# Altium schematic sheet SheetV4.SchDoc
size A1
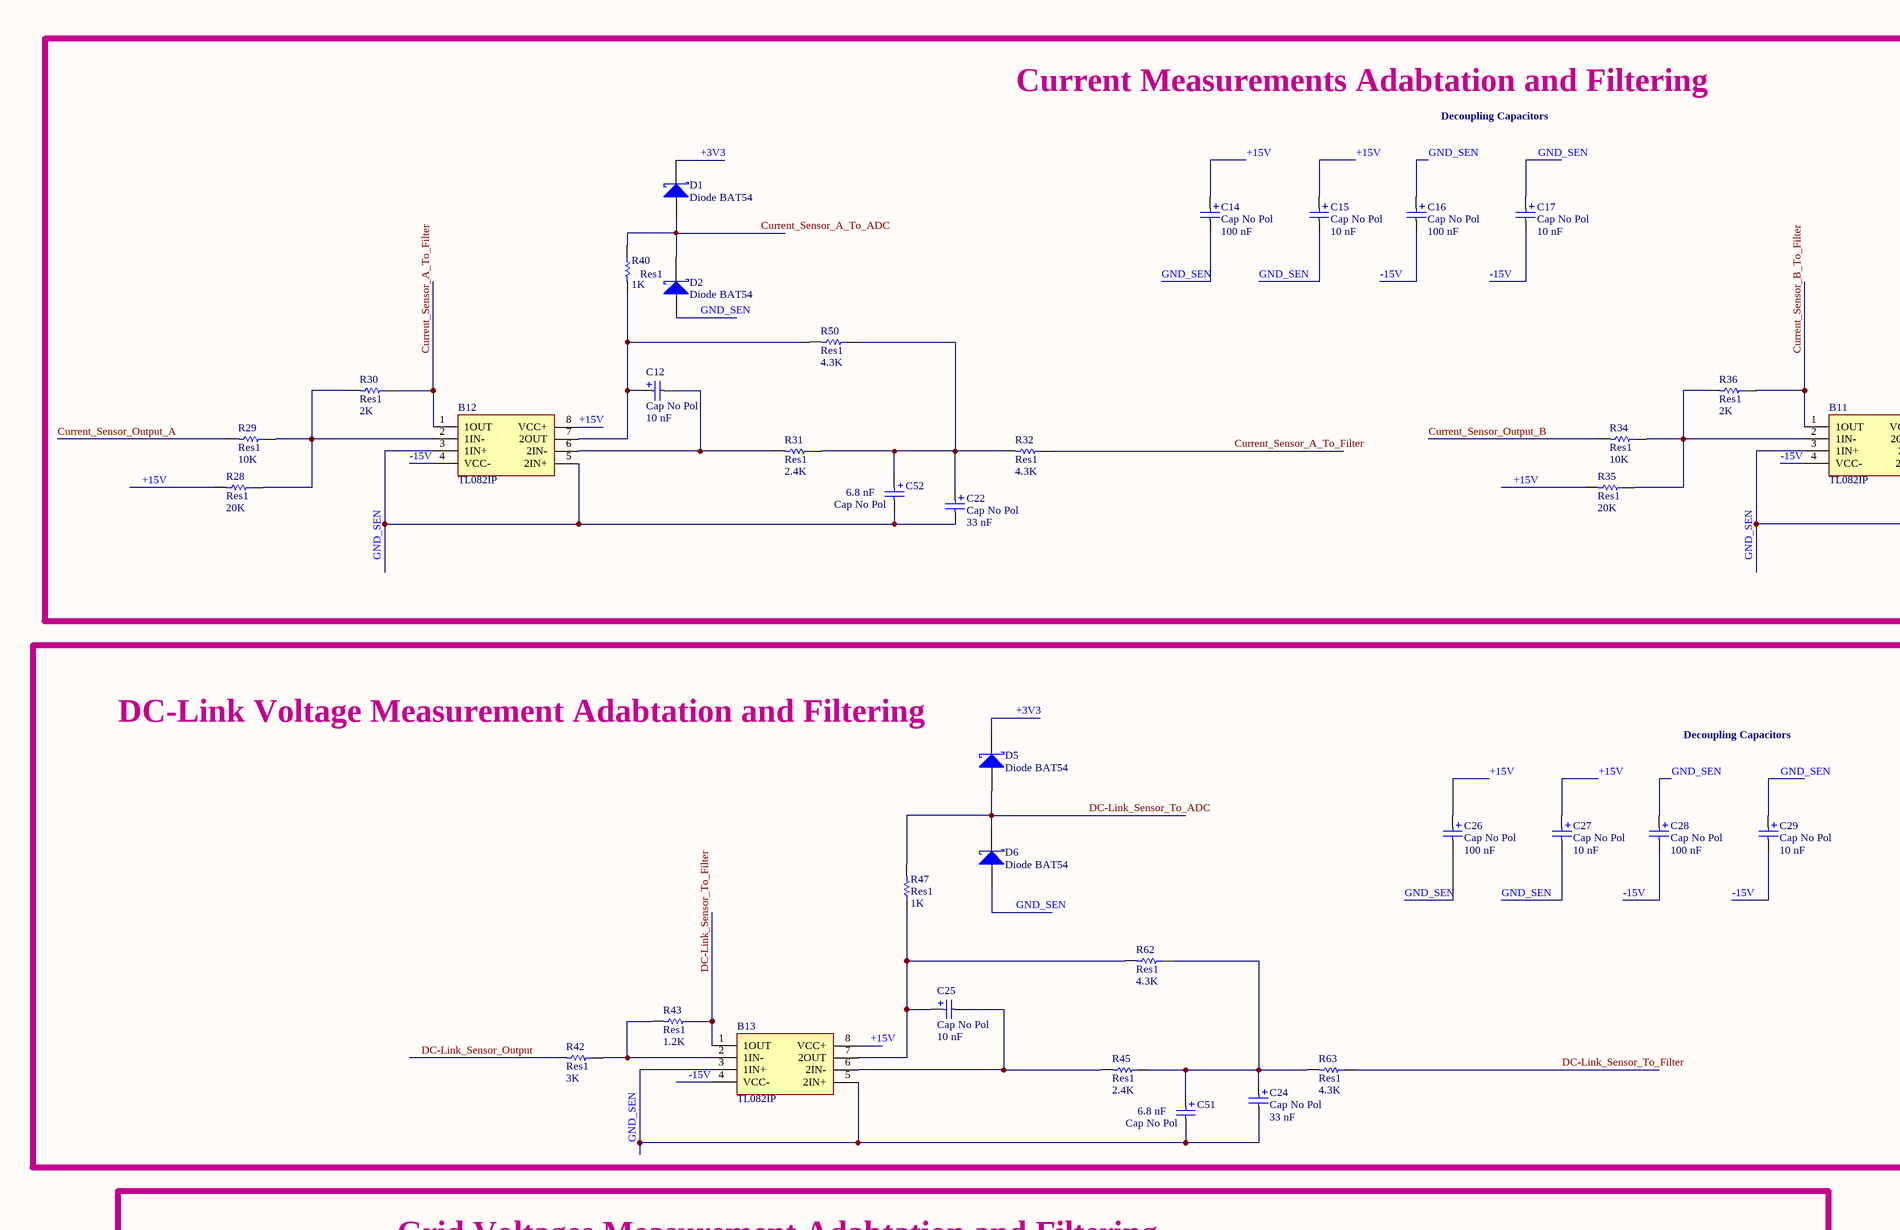
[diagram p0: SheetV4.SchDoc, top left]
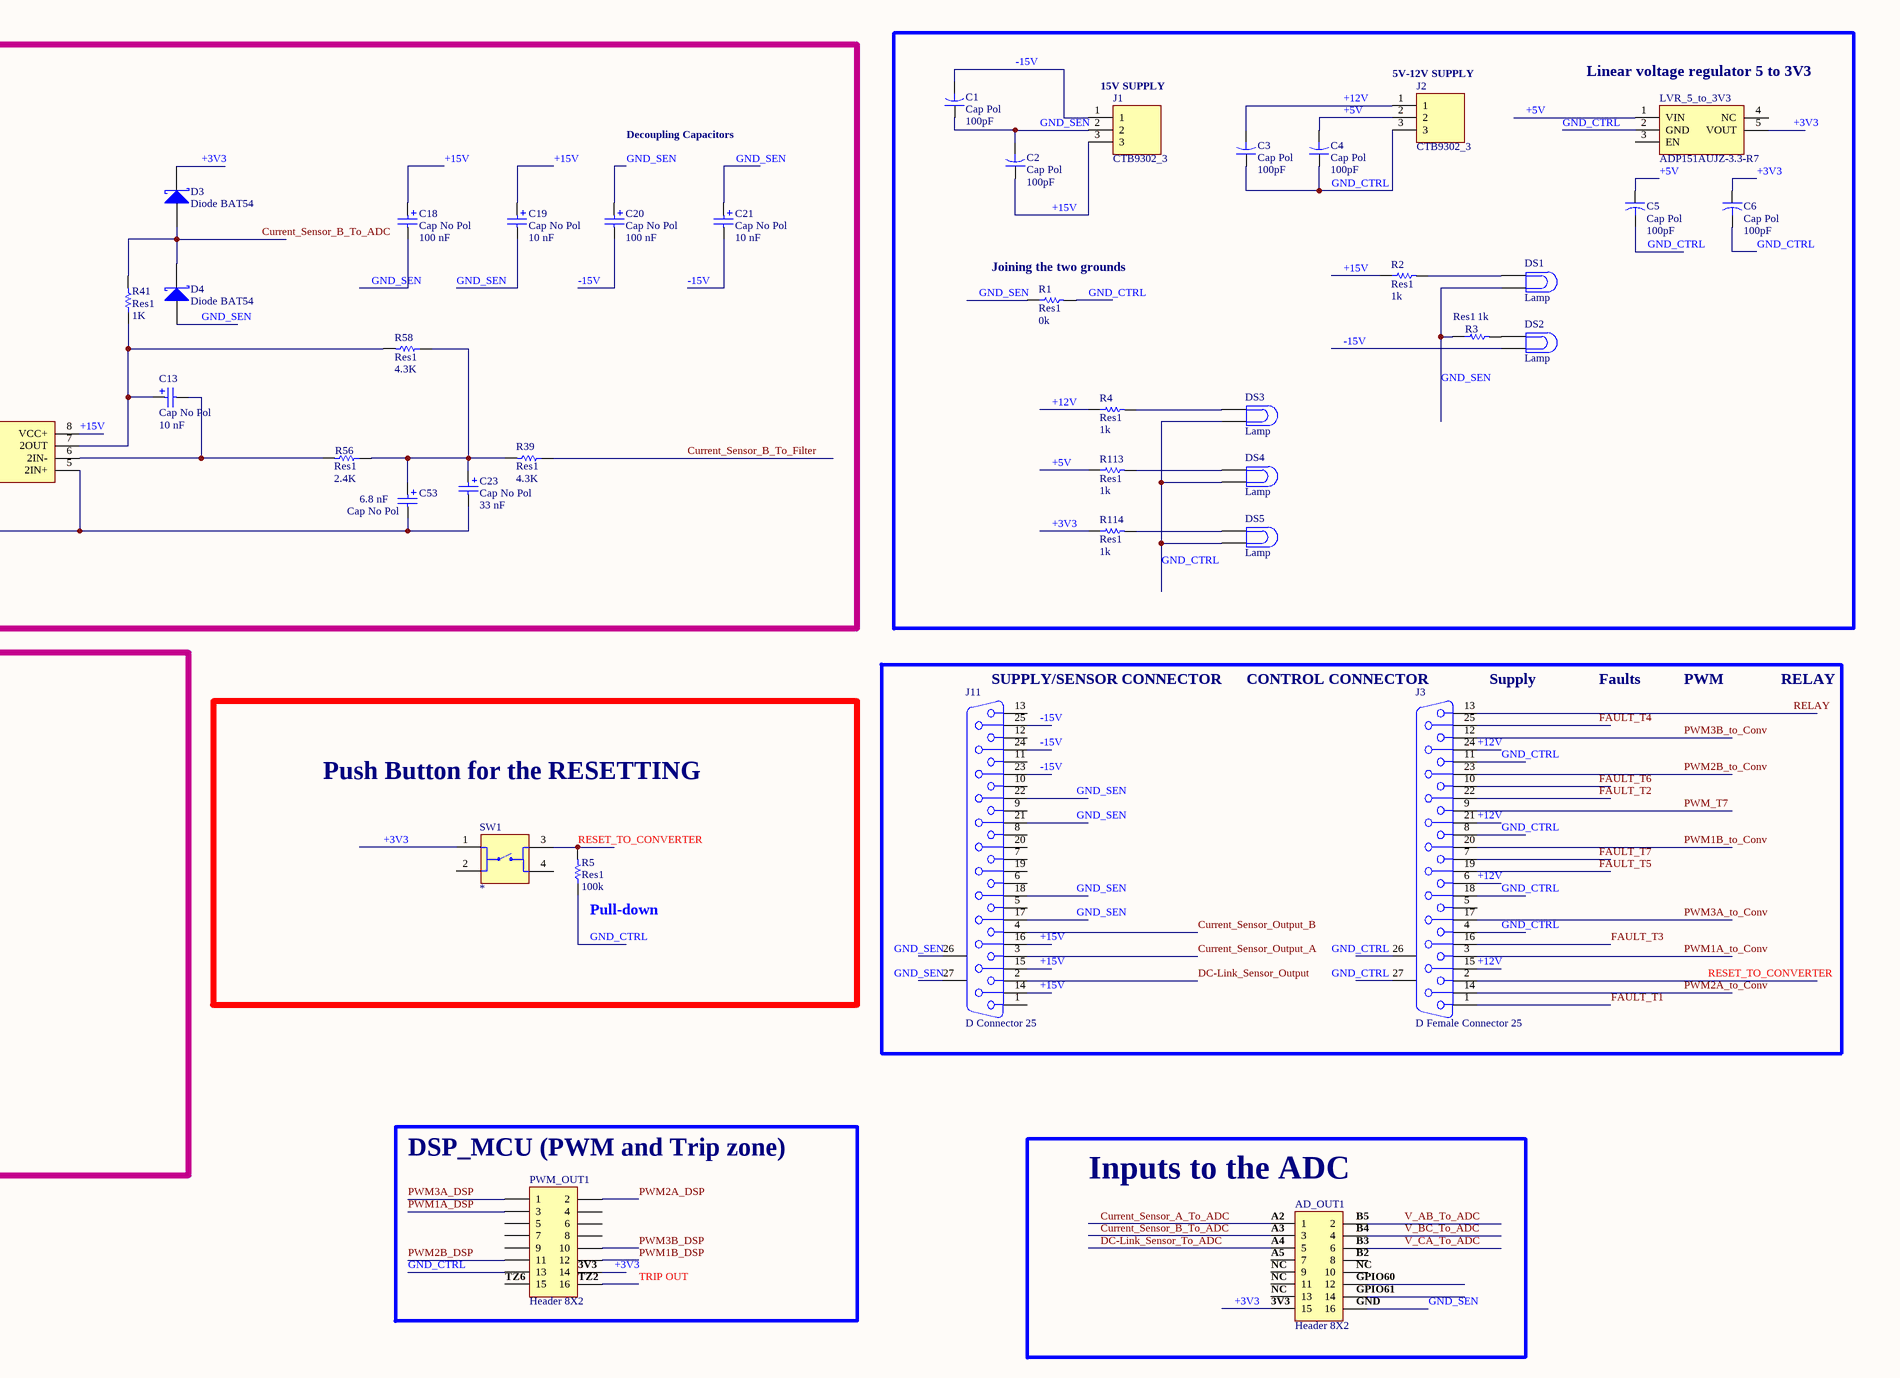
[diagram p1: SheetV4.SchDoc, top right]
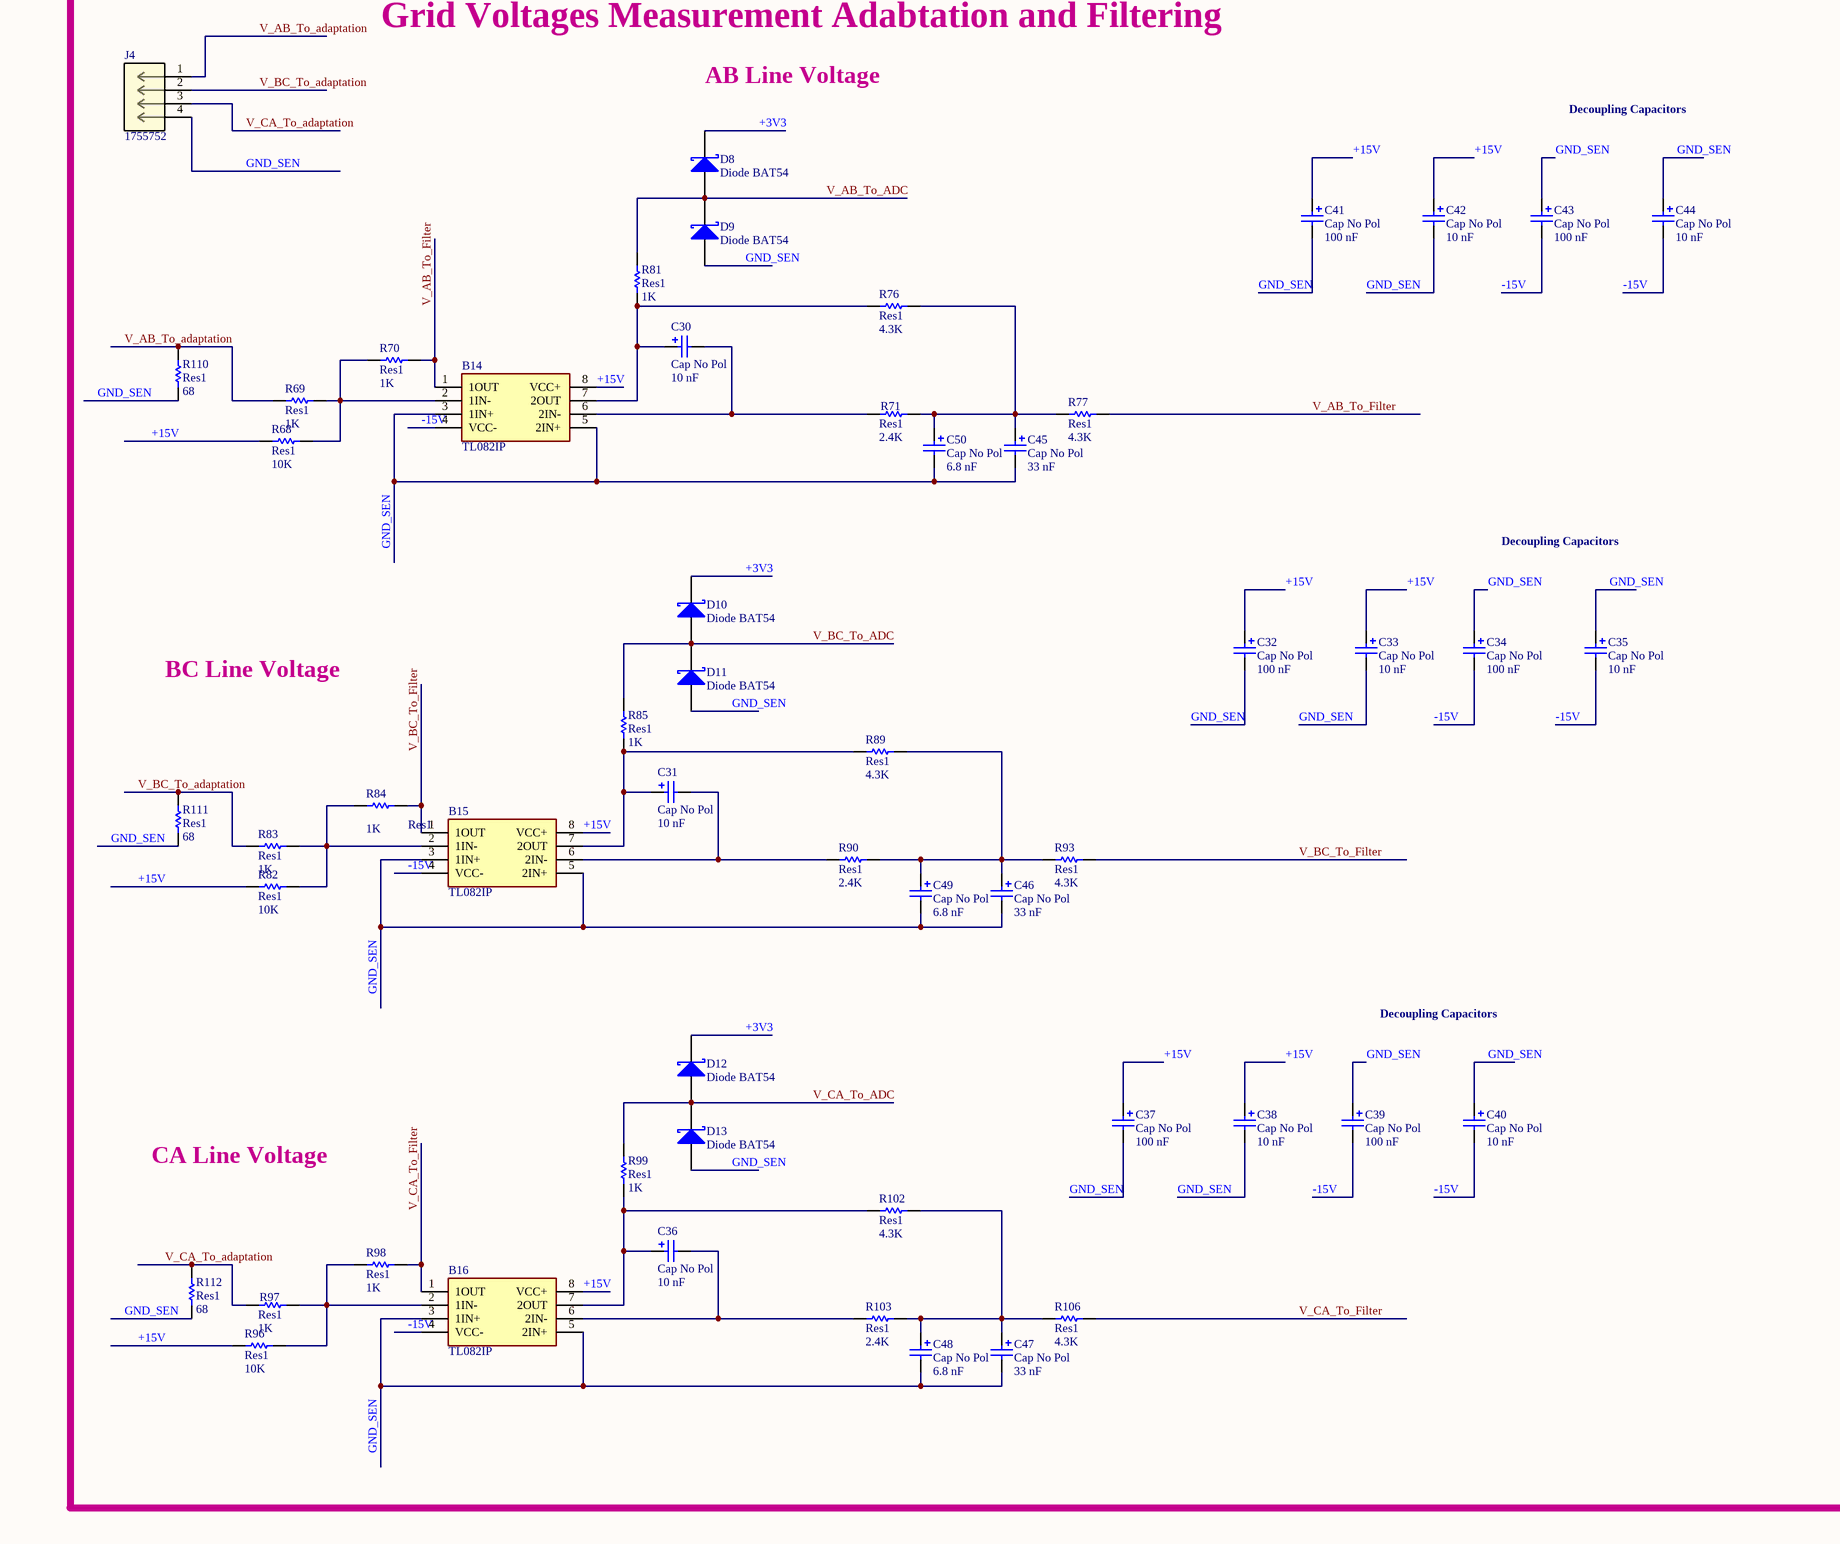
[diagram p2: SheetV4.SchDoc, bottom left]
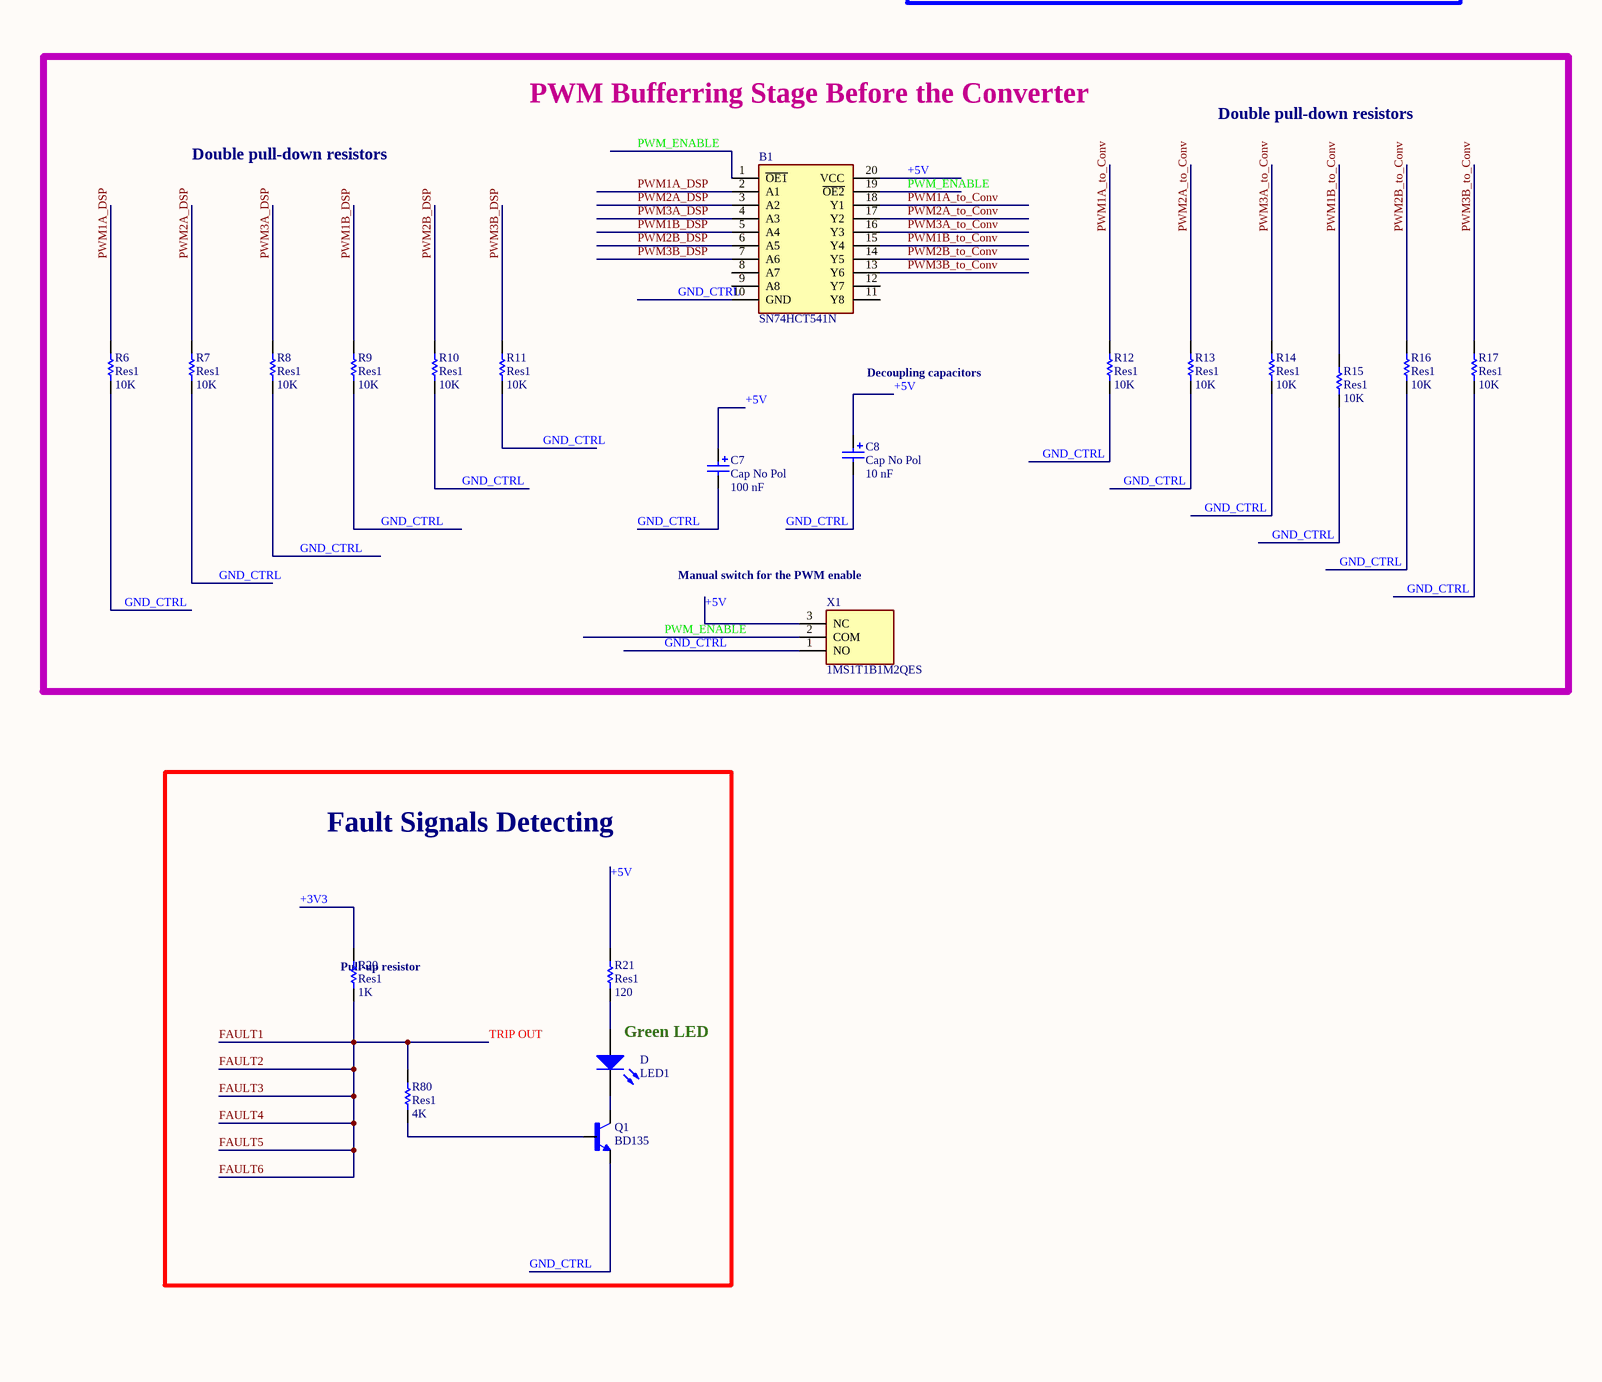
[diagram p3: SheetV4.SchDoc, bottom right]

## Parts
AD_OUT1  Header 8X2  [HDR2X8]
B1  SN74HCT541N  [DIP794W53P254L2540H508Q20N]
B11  TL082IP  [DIP794W53P254L959H508Q8N]
B12  TL082IP  [DIP794W53P254L959H508Q8N]
B13  TL082IP  [DIP794W53P254L959H508Q8N]
B14  TL082IP  [DIP794W53P254L959H508Q8N]
B15  TL082IP  [DIP794W53P254L959H508Q8N]
B16  TL082IP  [DIP794W53P254L959H508Q8N]
C1  Cap Pol  value 100pF  [CAPR5-4X5]
C2  Cap Pol  value 100pF  [CAPR5-4X5]
C3  Cap Pol  value 100pF  [CAPR5-4X5]
C4  Cap Pol  value 100pF  [CAPR5-4X5]
C5  Cap Pol  value 100pF  [CAPR5-4X5]
C6  Cap Pol  value 100pF  [CAPR5-4X5]
C7  Cap No Pol  value 100 nF  [RAD-0.1]
C8  Cap No Pol  value 10 nF  [RAD-0.1]
C12  Cap No Pol  value 10 nF  [RAD-0.1]
C13  Cap No Pol  value 10 nF  [RAD-0.1]
C14  Cap No Pol  value 100 nF  [RAD-0.1]
C15  Cap No Pol  value 10 nF  [RAD-0.1]
C16  Cap No Pol  value 100 nF  [RAD-0.1]
C17  Cap No Pol  value 10 nF  [RAD-0.1]
C18  Cap No Pol  value 100 nF  [RAD-0.1]
C19  Cap No Pol  value 10 nF  [RAD-0.1]
C20  Cap No Pol  value 100 nF  [RAD-0.1]
C21  Cap No Pol  value 10 nF  [RAD-0.1]
C22  Cap No Pol  value 33 nF  [RAD-0.1]
C23  Cap No Pol  value 33 nF  [RAD-0.1]
C24  Cap No Pol  value 33 nF  [RAD-0.1]
C25  Cap No Pol  value 10 nF  [RAD-0.1]
C26  Cap No Pol  value 100 nF  [RAD-0.1]
C27  Cap No Pol  value 10 nF  [RAD-0.1]
C28  Cap No Pol  value 100 nF  [RAD-0.1]
C29  Cap No Pol  value 10 nF  [RAD-0.1]
C30  Cap No Pol  value 10 nF  [RAD-0.1]
C31  Cap No Pol  value 10 nF  [RAD-0.1]
C32  Cap No Pol  value 100 nF  [RAD-0.1]
C33  Cap No Pol  value 10 nF  [RAD-0.1]
C34  Cap No Pol  value 100 nF  [RAD-0.1]
C35  Cap No Pol  value 10 nF  [RAD-0.1]
C36  Cap No Pol  value 10 nF  [RAD-0.1]
C37  Cap No Pol  value 100 nF  [RAD-0.1]
C38  Cap No Pol  value 10 nF  [RAD-0.1]
C39  Cap No Pol  value 100 nF  [RAD-0.1]
C40  Cap No Pol  value 10 nF  [RAD-0.1]
C41  Cap No Pol  value 100 nF  [RAD-0.1]
C42  Cap No Pol  value 10 nF  [RAD-0.1]
C43  Cap No Pol  value 100 nF  [RAD-0.1]
C44  Cap No Pol  value 10 nF  [RAD-0.1]
C45  Cap No Pol  value 33 nF  [RAD-0.1]
C46  Cap No Pol  value 33 nF  [RAD-0.1]
C47  Cap No Pol  value 33 nF  [RAD-0.1]
C48  Cap No Pol  value 6.8 nF  [RAD-0.1]
C49  Cap No Pol  value 6.8 nF  [RAD-0.1]
C50  Cap No Pol  value 6.8 nF  [RAD-0.1]
C51  Cap No Pol  value 6.8 nF  [RAD-0.1]
C52  Cap No Pol  value 6.8 nF  [RAD-0.1]
C53  Cap No Pol  value 6.8 nF  [RAD-0.1]
D  LED1  [LED-1]
D1  Diode BAT54  [DO-204AL]
D2  Diode BAT54  [DO-204AL]
D3  Diode BAT54  [DO-204AL]
D4  Diode BAT54  [DO-204AL]
D5  Diode BAT54  [DO-204AL]
D6  Diode BAT54  [DO-204AL]
D8  Diode BAT54  [DO-204AL]
D9  Diode BAT54  [DO-204AL]
D10  Diode BAT54  [DO-204AL]
D11  Diode BAT54  [DO-204AL]
D12  Diode BAT54  [DO-204AL]
D13  Diode BAT54  [DO-204AL]
DS1  Lamp  [PIN2]
DS2  Lamp  [PIN2]
DS3  Lamp  [PIN2]
DS4  Lamp  [PIN2]
DS5  Lamp  [PIN2]
J1  CTB9302_3  [SHDR3W100P0X500_1X3_1620X830X1230P]
J2  CTB9302_3  [SHDR3W100P0X500_1X3_1620X830X1230P]
J3  D Female Connector 25  [DSUB1.385-2H25B]
J4  1755752  [CONN_1924321]
J11  D Connector 25  [DSUB1.385-2H25A]
LVR_5_to_3V3  ADP151AUJZ-3.3-R7  [SOT95P280X100-5N]
PWM_OUT1  Header 8X2  [HDR2X8]
Q1  BD135  [TO229P780X300X2000-3]
R1  Res1  value 0k  [AXIAL-0.3]
R2  Res1  value 1k  [AXIAL-0.3]
R3  Res1  value 1k  [AXIAL-0.3]
R4  Res1  value 1k  [AXIAL-0.3]
R5  Res1  value 100k  [AXIAL-0.3]
R6  Res1  value 10K  [AXIAL-0.3]
R7  Res1  value 10K  [AXIAL-0.3]
R8  Res1  value 10K  [AXIAL-0.3]
R9  Res1  value 10K  [AXIAL-0.3]
R10  Res1  value 10K  [AXIAL-0.3]
R11  Res1  value 10K  [AXIAL-0.3]
R12  Res1  value 10K  [AXIAL-0.3]
R13  Res1  value 10K  [AXIAL-0.3]
R14  Res1  value 10K  [AXIAL-0.3]
R15  Res1  value 10K  [AXIAL-0.3]
R16  Res1  value 10K  [AXIAL-0.3]
R17  Res1  value 10K  [AXIAL-0.3]
R20  Res1  value 1K  [AXIAL-0.3]
R21  Res1  value 120  [AXIAL-0.3]
R28  Res1  value 20K  [AXIAL-0.3]
R29  Res1  value 10K  [AXIAL-0.3]
R30  Res1  value 2K  [AXIAL-0.3]
R31  Res1  value 2.4K  [AXIAL-0.3]
R32  Res1  value 4.3K  [AXIAL-0.3]
R34  Res1  value 10K  [AXIAL-0.3]
R35  Res1  value 20K  [AXIAL-0.3]
R36  Res1  value 2K  [AXIAL-0.3]
R39  Res1  value 4.3K  [AXIAL-0.3]
R40  Res1  value 1K  [AXIAL-0.3]
R41  Res1  value 1K  [AXIAL-0.3]
R42  Res1  value 3K  [AXIAL-0.3]
R43  Res1  value 1.2K  [AXIAL-0.3]
R45  Res1  value 2.4K  [AXIAL-0.3]
R47  Res1  value 1K  [AXIAL-0.3]
R50  Res1  value 4.3K  [AXIAL-0.3]
R56  Res1  value 2.4K  [AXIAL-0.3]
R58  Res1  value 4.3K  [AXIAL-0.3]
R62  Res1  value 4.3K  [AXIAL-0.3]
R63  Res1  value 4.3K  [AXIAL-0.3]
R68  Res1  value 10K  [AXIAL-0.3]
R69  Res1  value 1K  [AXIAL-0.3]
R70  Res1  value 1K  [AXIAL-0.3]
R71  Res1  value 2.4K  [AXIAL-0.3]
R76  Res1  value 4.3K  [AXIAL-0.3]
R77  Res1  value 4.3K  [AXIAL-0.3]
R80  Res1  value 4K  [AXIAL-0.3]
R81  Res1  value 1K  [AXIAL-0.3]
R82  Res1  value 10K  [AXIAL-0.3]
R83  Res1  value 1K  [AXIAL-0.3]
R84  Res1  value 1K  [AXIAL-0.3]
R85  Res1  value 1K  [AXIAL-0.3]
R89  Res1  value 4.3K  [AXIAL-0.3]
R90  Res1  value 2.4K  [AXIAL-0.3]
R93  Res1  value 4.3K  [AXIAL-0.3]
R96  Res1  value 10K  [AXIAL-0.3]
R97  Res1  value 1K  [AXIAL-0.3]
R98  Res1  value 1K  [AXIAL-0.3]
R99  Res1  value 1K  [AXIAL-0.3]
R102  Res1  value 4.3K  [AXIAL-0.3]
R103  Res1  value 2.4K  [AXIAL-0.3]
R106  Res1  value 4.3K  [AXIAL-0.3]
R110  Res1  value 68  [AXIAL-0.3]
R111  Res1  value 68  [AXIAL-0.3]
R112  Res1  value 68  [AXIAL-0.3]
R113  Res1  value 1k  [AXIAL-0.3]
R114  Res1  value 1k  [AXIAL-0.3]
SW1  1825910-6  [SW_1825910-6-4]  (value not drawn)
X1  1MS1T1B1M2QES  [1MS1T1B1M2QES]

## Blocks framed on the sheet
Current Measurements Adabtation and Filtering: B11 B12 C12-C23 C52 C53 D1-D4 R28-R32 R34-R36 R39-R41 R50 R56 R58
Linear voltage regulator 5 to 3V3: C1-C6 DS1-DS5 J1 J2 LVR_5_to_3V3 R1-R4 R113 R114
DC-Link Voltage Measurement Adabtation and Filtering: B13 C24-C29 C51 D5 D6 R42 R43 R45 R47 R62 R63
Push Button for the RESETTING: R5 SW1
DSP_MCU (PWM and Trip zone): PWM_OUT1
Inputs to the ADC: AD_OUT1
Grid Voltages Measurement Adabtation and Filtering: B14-B16 C30-C50 D8-D13 J4 R68-R71 R76 R77 R81-R85 R89 R90 R93 R96-R99 R102 R103 R106 R110-R112
PWM Bufferring Stage Before the Converter: B1 C7 C8 R6-R17 X1
Fault Signals Detecting: D Q1 R20 R21 R80

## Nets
+3V3: AD_OUT1.15 C6.1 D1.2(K) D3.2(K) D5.2(K) D8.2(K) D10.2(K) D12.2(K) LVR_5_to_3V3.5(VOUT) PWM_OUT1.14 R20.2 R114.1 SW1.1
+5V: B1.20(VCC) C4.2 C5.1 C7.1 C8.1 J2.2 LVR_5_to_3V3.1(VIN) R21.2 R113.1 X1.3(NC)
+12V: C3.2 J2.1 J3.6 J3.15 J3.21 J3.24 R4.1
+15V: B11.8(VCC+) B12.8(VCC+) B13.8(VCC+) B14.8(VCC+) B15.8(VCC+) B16.8(VCC+) C2.1 C14.1 C15.1 C18.1 C19.1 C26.1 C27.1 C32.1 C33.1 C37.1 C38.1 C41.1 C42.1 J1.3 J11.14 J11.15 J11.16 R2.1 R28.2 R35.2 R68.2 R82.2 R96.2
-15V: B11.4(VCC-) B12.4(VCC-) B13.4(VCC-) B14.4(VCC-) B15.4(VCC-) B16.4(VCC-) C1.2 C16.2 C17.2 C20.2 C21.2 C28.2 C29.2 C34.2 C35.2 C39.2 C40.2 C43.2 C44.2 DS2.2 J1.1 J11.23 J11.24 J11.25
Current_Sensor_A_To_ADC: AD_OUT1.1 D1.1(A) D2.2(K) R40.1
Current_Sensor_A_To_Filter: B12.1(1OUT) R30.1 R32.1
Current_Sensor_B_To_ADC: AD_OUT1.3 D3.1(A) D4.2(K) R41.2
Current_Sensor_B_To_Filter: B11.1(1OUT) R36.1 R39.1
Current_Sensor_Output_A: J11.3 R29.2
Current_Sensor_Output_B: J11.4 R34.2
DC-Link_Sensor_Output: J11.2 R42.2
DC-Link_Sensor_To_ADC: AD_OUT1.5 D5.1(A) D6.2(K) R47.2
DC-Link_Sensor_To_Filter: B13.1(1OUT) R43.1 R63.1
FAULT1: PWM_OUT1.16 R20.1 R80.2  [also labelled FAULT2, FAULT3, FAULT4, FAULT5, FAULT6, TRIP OUT]
FAULT_T1: J3.1
FAULT_T2: J3.22
FAULT_T3: J3.16
FAULT_T4: J3.25
FAULT_T5: J3.19
FAULT_T6: J3.10
FAULT_T7: J3.7
GND_CTRL: B1.10(GND) C3.1 C4.1 C5.2 C6.2 C7.2 C8.2 DS3.2 DS4.2 DS5.2 J2.3 J3.4 J3.8 J3.11 J3.18 LVR_5_to_3V3.2(GND) PWM_OUT1.13 Q1.1(E) R1.2 R5.1 R6.1 R7.1 R8.1 R9.1 R10.1 R11.1 R12.1 R13.1 R14.1 R15.1 R16.1 R17.1 X1.1(NO)
GND_SEN: AD_OUT1.16 B11.3(1IN+) B11.5(2IN+) B12.3(1IN+) B12.5(2IN+) B13.3(1IN+) B13.5(2IN+) B14.3(1IN+) B14.5(2IN+) B15.3(1IN+) B15.5(2IN+) B16.3(1IN+) B16.5(2IN+) C1.1 C2.2 C14.2 C15.2 C16.1 C17.1 C18.2 C19.2 C20.1 C21.1 C22.2 C23.2 C24.2 C26.2 C27.2 C28.1 C29.1 C32.2 C33.2 C34.1 C35.1 C37.2 C38.2 C39.1 C40.1 C41.2 C42.2 C43.1 C44.1 C45.2 C46.2 C47.2 C48.2 C49.2 C50.2 C51.2 C52.2 C53.2 D2.1(A) D4.1(A) D6.1(A) D9.1(A) D11.1(A) D13.1(A) DS1.2 J1.2 J4.4 J11.17 J11.18 J11.21 J11.22 R1.1 R3.1 R110.2 R111.2 R112.2
PWM1A_DSP: B1.2(A1) PWM_OUT1.3 R6.2
PWM1A_to_Conv: B1.18(Y1) J3.3 R12.2
PWM1B_DSP: B1.5(A4) PWM_OUT1.12 R9.2
PWM1B_to_Conv: B1.15(Y4) J3.20 R15.2
PWM2A_DSP: B1.3(A2) PWM_OUT1.2 R7.2
PWM2A_to_Conv: B1.17(Y2) J3.14 R13.2
PWM2B_DSP: B1.6(A5) PWM_OUT1.11 R10.2
PWM2B_to_Conv: B1.14(Y5) J3.23 R16.2
PWM3A_DSP: B1.4(A3) PWM_OUT1.1 R8.2
PWM3A_to_Conv: B1.16(Y3) J3.17 R14.2
PWM3B_DSP: B1.7(A6) PWM_OUT1.10 R11.2
PWM3B_to_Conv: B1.13(Y6) J3.12 R17.2
PWM_ENABLE: B1.1(~{OE1}) B1.19(~{OE2}) X1.2(COM)
PWM_T7: J3.9
RELAY: J3.13
RESET_TO_CONVERTER: J3.2 R5.2 SW1.3
V_AB_To_adaptation: J4.1 R69.2 R110.1
V_AB_To_ADC: AD_OUT1.2 D8.1(A) D9.2(K) R81.2
V_AB_To_Filter: B14.1(1OUT) R70.1 R77.1
V_BC_To_adaptation: J4.2 R83.2 R111.1
V_BC_To_ADC: AD_OUT1.4 D10.1(A) D11.2(K) R85.2
V_BC_To_Filter: B15.1(1OUT) R84.1 R93.1
V_CA_To_adaptation: J4.3 R97.2 R112.1
V_CA_To_ADC: AD_OUT1.6 D12.1(A) D13.2(K) R99.2
V_CA_To_Filter: B16.1(1OUT) R98.1 R106.1
NetB11_2: B11.2(1IN-) R34.1 R35.1 R36.2
NetB11_6: B11.6(2IN-) C13.2 R56.2
NetB11_7: B11.7(2OUT) C13.1 R41.1 R58.2
NetB12_2: B12.2(1IN-) R28.1 R29.1 R30.2
NetB12_6: B12.6(2IN-) C12.2 R31.2
NetB12_7: B12.7(2OUT) C12.1 R40.2 R50.2
NetB13_2: B13.2(1IN-) R42.1 R43.2
NetB13_6: B13.6(2IN-) C25.2 R45.2
NetB13_7: B13.7(2OUT) C25.1 R47.1 R62.2
NetB14_2: B14.2(1IN-) R68.1 R69.1 R70.2
NetB14_6: B14.6(2IN-) C30.2 R71.2
NetB14_7: B14.7(2OUT) C30.1 R76.2 R81.1
NetB15_2: B15.2(1IN-) R82.1 R83.1 R84.2
NetB15_6: B15.6(2IN-) C31.2 R90.2
NetB15_7: B15.7(2OUT) C31.1 R85.1 R89.2
NetB16_2: B16.2(1IN-) R96.1 R97.1 R98.2
NetB16_6: B16.6(2IN-) C36.2 R103.2
NetB16_7: B16.7(2OUT) C36.1 R99.1 R102.2
NetC22_1: C22.1 C52.1 R31.1 R32.2 R50.1
NetC23_1: C23.1 C53.1 R39.2 R56.1 R58.1
NetC24_1: C24.1 C51.1 R45.1 R62.1 R63.2
NetC45_1: C45.1 C50.1 R71.1 R76.1 R77.2
NetC46_1: C46.1 C49.1 R89.1 R90.1 R93.2
NetC47_1: C47.1 C48.1 R102.1 R103.1 R106.2
NetD_1: D.1(A) R21.1
NetD_2: D.2(K) Q1.2(C)
NetDS1_1: DS1.1 R2.2
NetDS2_1: DS2.1 R3.2
NetDS3_1: DS3.1 R4.2
NetDS4_1: DS4.1 R113.2
NetDS5_1: DS5.1 R114.2
NetQ1_3: Q1.3(B) R80.1

Not connected (* = marked no-connect by the designer): AD_OUT1 7 8 9 10 11 12 13 14; B1 8(A7) 9(A8) 11(Y8) 12(Y7); J3 5 26(MH1) 27(MH2); J11 1 5 6 7 8 9 10 11 12 13 19 20 26(MH1) 27(MH2); LVR_5_to_3V3 3(EN) 4(NC); PWM_OUT1 4 5 6 7 8 9 15; SW1 2 4

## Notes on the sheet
- Decoupling Capacitors
- (near J1) 15V SUPPLY
- (near J2) 5V-12V SUPPLY
- (near R1) Joining the two grounds
- (near J11) SUPPLY/SENSOR CONNECTOR
- (near J3) CONTROL CONNECTOR
- (near J3) Supply
- Faults
- PWM
- RELAY
- (near R5) Pull-down
- (near AD_OUT1) A2
- (near AD_OUT1) B5
- (near PWM_OUT1) TZ6
- (near PWM_OUT1) 3V3
- (near PWM_OUT1) TZ2
- (near AD_OUT1) A3
- (near AD_OUT1) A4
- (near AD_OUT1) A5
- (near AD_OUT1) NC
- (near AD_OUT1) B2
- (near AD_OUT1) B3
- (near AD_OUT1) B4
- (near AD_OUT1) GPIO60
- AB Line Voltage
- (near AD_OUT1) 3V3
- (near AD_OUT1) GPIO61
- (near AD_OUT1) GND
- Double pull-down resistors
- Decoupling capacitors
- BC Line Voltage
- (near X1) Manual switch for the PWM enable
- (near R20) Pull-up resistor
- CA Line Voltage
- (near D) Green LED
- Labels drawn without touching a wire or pin: GND_CTRL, GND_SEN

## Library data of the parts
AD_OUT1 PWM_OUT1 = Header 8X2: Header, 8-Pin, Dual row
B1 = SN74HCT541N: Octal Buffers and Line Drivers With 3-State Outputs; Manufacturer_Name: Texas Instruments; Geometry.Height: 5.08mm
B11-B16 = TL082IP: TL082IP, Dual Operational Amplifier 3MHz, 8-Pin PDIP; Manufacturer_Name: Texas Instruments; Geometry.Height: 5.08mm
C1-C6 = Cap Pol: Capacitor
C7 C8 C12-C53 = Cap No Pol: Polarized Capacitor (Radial)
D = LED1: Typical RED GaAs LED
D1-D6 D8-D13 = Diode Zener: Zener
DS1-DS5 = Lamp: Incandescent Bulb
J1 J2 = CTB9302_3: RS PRO 5mm Pitch Vertical PCB Terminal Block, PCB Header, PCB Mount, 3 Way; Manufacturer_Name: RS Pro; Manufacturer_Part_Number: CTB9302/3; Geometry.Height: 12.3mm
J3 = D Female Connector 25: Receptacle Assembly, 25 Position, Right Angle; PackageDocument: U; Positions: 25
J4 = 1755752: No Description Available; Mfr_Name: Phoenix Contact
J11 = D Connector 25: Receptacle Assembly, 25 Position, Right Angle; PackageDocument: U; Positions: 25
LVR_5_to_3V3 = ADP151AUJZ-3.3-R7: Analog Devices ADP151AUJZ-3.3-R7, Single Linear Voltage Regulator, 200mA 3.3 V, +/-2.5%, 5-Pin TSOT; Geometry.Height: 1mm
Q1 = BD135: TRANSISTOR, NPN, TO-126; Transistor Polarity:NPN; Collector Emitter Voltage V(br)ceo:45V; Power Dissipation Pd:12.5W; DC Collector Current:1A; DC Current Gain hFE:40; Transistor Case Style:TO-126; No. of Pins:3; SVHC:No SVHC (18-Jun-2012); Collector Emitter Voltage Vces:500mV; Continuous Collector Current Ic Max:1A; Current Ic Continuous a Max:1A; Current Ic hFE:150mA; Full Power Rating Temperature:25Â°C; Hfe Min:40; No. of Transistors:1; Package / Case:TO-126; Power Dissipation Pd:12.5W; Power Dissipation Ptot Max:12.5W; Termination Type:Through Hole; Voltage Vcbo:45V; MF: ON Semiconductor
R1-R17 R20 R21 R28-R32 R34-R36 R39-R43 R45 R47 R50 R56 R58 R62 R63 R68-R71 R76 R77 R80-R85 R89 R90 R93 R96-R99 R102 R103 R106 R110-R114 = Res1: Resistor
SW1 = 1825910-6: Switch Push Button OFF (ON) SPST Round Button 0.05A 24VDC Momentary Contact PC Pins Thru-Hole; MF: TE Connectivity
X1 = 1MS1T1B1M2QES: Toggle Switches SWITCH TOGGLE SPDT; Manufacturer_Name: Dailywell; Geometry.Height: 28.19mm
